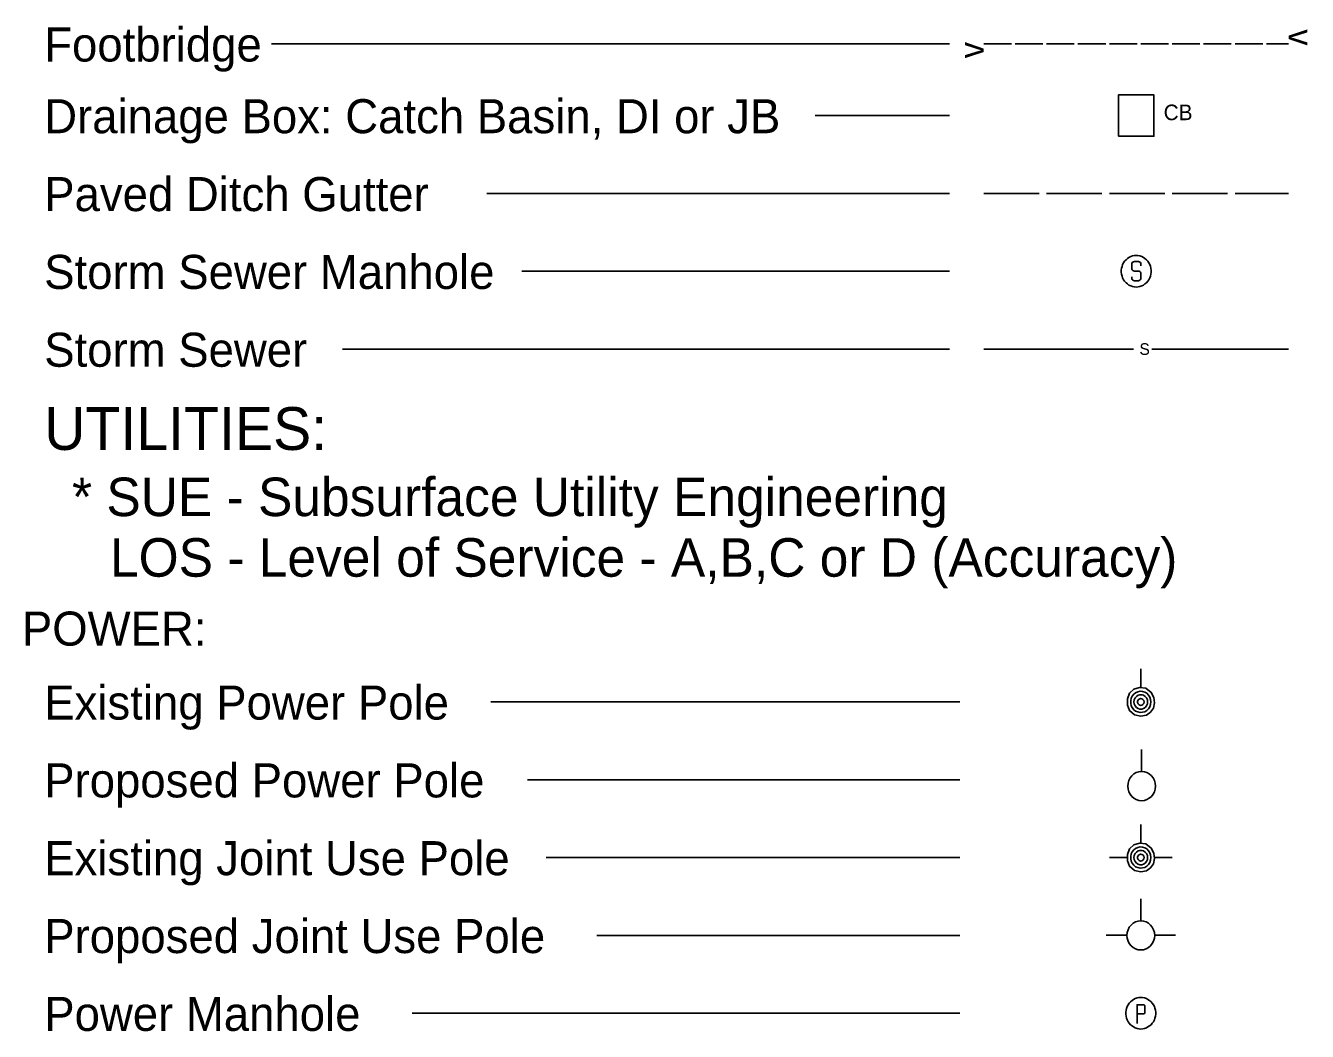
# Model space of a CAD drawing. Extents: x 2025847 to 2026166, y 840763 to 840870.
# Drawn here: x 2026099 to 2026127.55, y 840824.21 to 840846.6 of the extents above; entities that cross this region are included whole.
import ezdxf

# ---------------------------------------------------------------- set-up
doc = ezdxf.new("R2010")
doc.units = 0
doc.layers.add('Sheet_Symbology', color=7, linetype='Continuous')

msp = doc.modelspace()

# ---------------------------------------------------------------- linework, layer by layer
at = {"layer": 'Sheet_Symbology'}
for p, q in [((2026119.578, 840846.199), (2026104.475, 840846.199)), ((2026120.343, 840846.199), (2026120.961, 840846.199)), ((2026121.043, 840846.199), (2026121.66, 840846.199)), ((2026121.743, 840846.199), (2026122.36, 840846.199)), ((2026122.442, 840846.199), (2026123.06, 840846.199)), ((2026123.142, 840846.199), (2026123.759, 840846.199)), ((2026123.842, 840846.199), (2026124.459, 840846.199)), ((2026124.541, 840846.199), (2026125.159, 840846.199)), ((2026125.241, 840846.199), (2026125.858, 840846.199)), ((2026125.941, 840846.199), (2026126.558, 840846.199)), ((2026126.64, 840846.199), (2026127.134, 840846.199)), ((2026119.578, 840844.602), (2026116.59, 840844.602)), ((2026119.578, 840842.869), (2026109.273, 840842.869)), ((2026120.343, 840842.869), (2026121.578, 840842.869)), ((2026121.743, 840842.869), (2026122.977, 840842.869)), ((2026123.142, 840842.869), (2026124.377, 840842.869)), ((2026124.541, 840842.869), (2026125.776, 840842.869)), ((2026125.941, 840842.869), (2026127.134, 840842.869)), ((2026123.64, 840841.198), (2026123.64, 840841.291)), ((2026123.699, 840841.353), (2026123.787, 840841.353)), ((2026123.843, 840841.291), (2026123.843, 840841.26)), ((2026119.578, 840841.136), (2026110.056, 840841.136)), ((2026123.64, 840841.015), (2026123.64, 840840.984)), ((2026123.787, 840841.139), (2026123.699, 840841.139)), ((2026123.699, 840840.925), (2026123.787, 840840.925)), ((2026123.843, 840840.984), (2026123.843, 840841.08)), ((2026119.578, 840839.403), (2026106.061, 840839.403)), ((2026120.343, 840839.403), (2026123.679, 840839.403)), ((2026124.091, 840839.403), (2026127.134, 840839.403)), ((2026123.842, 840831.865), (2026123.842, 840832.281)), ((2026119.807, 840831.546), (2026109.364, 840831.546)), ((2026123.859, 840829.996), (2026123.859, 840830.483)), ((2026119.807, 840829.813), (2026110.178, 840829.813)), ((2026123.842, 840828.399), (2026123.842, 840828.815)), ((2026119.807, 840828.08), (2026110.595, 840828.08)), ((2026123.538, 840828.08), (2026123.143, 840828.08)), ((2026124.146, 840828.08), (2026124.541, 840828.08)), ((2026123.842, 840826.673), (2026123.842, 840827.16)), ((2026119.807, 840826.347), (2026111.722, 840826.347)), ((2026123.533, 840826.348), (2026123.07, 840826.348)), ((2026124.15, 840826.348), (2026124.613, 840826.348)), ((2026123.935, 840824.774), (2026123.935, 840824.625)), ((2026119.807, 840824.614), (2026107.611, 840824.614)), ((2026123.909, 840824.597), (2026123.759, 840824.597))]:
    msp.add_line(p, q, dxfattribs=at)
for points in [[(2026123.343, 840844.142), (2026124.134, 840844.142), (2026124.134, 840845.063), (2026123.343, 840845.063)], [(2026123.842, 840831.226), (2026123.969, 840831.251), (2026124.054, 840831.315), (2026124.121, 840831.405), (2026124.146, 840831.526), (2026124.133, 840831.642), (2026124.073, 840831.757), (2026123.951, 840831.853), (2026123.811, 840831.865), (2026123.69, 840831.827), (2026123.593, 840831.737), (2026123.544, 840831.616), (2026123.544, 840831.475), (2026123.593, 840831.354), (2026123.702, 840831.258)], [(2026123.842, 840827.76), (2026123.969, 840827.785), (2026124.054, 840827.849), (2026124.121, 840827.939), (2026124.146, 840828.06), (2026124.133, 840828.176), (2026124.073, 840828.291), (2026123.951, 840828.387), (2026123.811, 840828.399), (2026123.69, 840828.361), (2026123.593, 840828.271), (2026123.544, 840828.15), (2026123.544, 840828.009), (2026123.593, 840827.888), (2026123.702, 840827.792)]]:
    msp.add_lwpolyline(points, close=True, dxfattribs=at)
for points in [[(2026123.739, 840841.488), (2026123.696, 840841.485), (2026123.656, 840841.477), (2026123.616, 840841.462), (2026123.578, 840841.443), (2026123.544, 840841.42), (2026123.512, 840841.392), (2026123.482, 840841.358), (2026123.458, 840841.325), (2026123.437, 840841.285), (2026123.423, 840841.243), (2026123.413, 840841.201), (2026123.407, 840841.158), (2026123.407, 840841.113), (2026123.413, 840841.071), (2026123.423, 840841.026), (2026123.437, 840840.987), (2026123.458, 840840.947), (2026123.482, 840840.914), (2026123.512, 840840.88), (2026123.544, 840840.852), (2026123.578, 840840.829), (2026123.616, 840840.81), (2026123.656, 840840.795), (2026123.699, 840840.787), (2026123.739, 840840.784), (2026123.782, 840840.787), (2026123.822, 840840.795), (2026123.862, 840840.81), (2026123.899, 840840.829), (2026123.934, 840840.852), (2026123.966, 840840.88), (2026123.996, 840840.914), (2026124.02, 840840.947), (2026124.041, 840840.987), (2026124.054, 840841.029), (2026124.065, 840841.071), (2026124.07, 840841.113), (2026124.07, 840841.158), (2026124.065, 840841.201), (2026124.054, 840841.246), (2026124.041, 840841.285), (2026124.02, 840841.325), (2026123.996, 840841.358), (2026123.966, 840841.392), (2026123.934, 840841.42), (2026123.899, 840841.443), (2026123.862, 840841.462), (2026123.822, 840841.477), (2026123.779, 840841.485), (2026123.739, 840841.488)], [(2026123.64, 840841.291), (2026123.645, 840841.311), (2026123.653, 840841.327), (2026123.664, 840841.339), (2026123.68, 840841.347), (2026123.699, 840841.353)], [(2026123.787, 840841.353), (2026123.803, 840841.347), (2026123.819, 840841.339), (2026123.832, 840841.327), (2026123.84, 840841.311), (2026123.843, 840841.291)], [(2026123.699, 840841.139), (2026123.68, 840841.142), (2026123.664, 840841.15), (2026123.653, 840841.164), (2026123.645, 840841.181), (2026123.64, 840841.198)], [(2026123.64, 840840.987), (2026123.645, 840840.967), (2026123.653, 840840.95), (2026123.664, 840840.936), (2026123.68, 840840.928), (2026123.699, 840840.925)], [(2026123.843, 840841.077), (2026123.84, 840841.097), (2026123.832, 840841.113), (2026123.819, 840841.128), (2026123.803, 840841.136), (2026123.787, 840841.139)], [(2026123.787, 840840.925), (2026123.803, 840840.928), (2026123.819, 840840.936), (2026123.832, 840840.95), (2026123.84, 840840.967), (2026123.843, 840840.987)], [(2026124.067, 840831.546), (2026124.06, 840831.603), (2026124.042, 840831.654), (2026124.012, 840831.699), (2026123.975, 840831.737), (2026123.933, 840831.763), (2026123.878, 840831.776), (2026123.829, 840831.782), (2026123.775, 840831.769), (2026123.726, 840831.75), (2026123.69, 840831.718), (2026123.653, 840831.673), (2026123.629, 840831.629), (2026123.617, 840831.571), (2026123.617, 840831.52), (2026123.629, 840831.462), (2026123.653, 840831.418), (2026123.69, 840831.373), (2026123.726, 840831.341), (2026123.775, 840831.322), (2026123.829, 840831.309), (2026123.878, 840831.315), (2026123.933, 840831.328), (2026123.975, 840831.354), (2026124.012, 840831.392), (2026124.042, 840831.437), (2026124.06, 840831.488), (2026124.067, 840831.546)], [(2026123.994, 840831.546), (2026123.988, 840831.59), (2026123.969, 840831.635), (2026123.939, 840831.667), (2026123.903, 840831.693), (2026123.866, 840831.705), (2026123.817, 840831.705), (2026123.781, 840831.693), (2026123.744, 840831.667), (2026123.714, 840831.635), (2026123.696, 840831.59), (2026123.69, 840831.546), (2026123.696, 840831.501), (2026123.714, 840831.456), (2026123.744, 840831.424), (2026123.781, 840831.398), (2026123.817, 840831.386), (2026123.866, 840831.386), (2026123.903, 840831.398), (2026123.939, 840831.424), (2026123.969, 840831.456), (2026123.988, 840831.501), (2026123.994, 840831.546)], [(2026123.915, 840831.546), (2026123.909, 840831.577), (2026123.89, 840831.603), (2026123.866, 840831.616), (2026123.836, 840831.622), (2026123.805, 840831.61), (2026123.781, 840831.59), (2026123.769, 840831.558), (2026123.769, 840831.533), (2026123.781, 840831.501), (2026123.805, 840831.481), (2026123.836, 840831.469), (2026123.866, 840831.475), (2026123.89, 840831.488), (2026123.909, 840831.514), (2026123.915, 840831.546)], [(2026124.067, 840828.08), (2026124.06, 840828.137), (2026124.042, 840828.188), (2026124.012, 840828.233), (2026123.975, 840828.271), (2026123.933, 840828.297), (2026123.878, 840828.31), (2026123.829, 840828.316), (2026123.775, 840828.303), (2026123.726, 840828.284), (2026123.69, 840828.252), (2026123.653, 840828.207), (2026123.629, 840828.163), (2026123.617, 840828.105), (2026123.617, 840828.054), (2026123.629, 840827.996), (2026123.653, 840827.952), (2026123.69, 840827.907), (2026123.726, 840827.875), (2026123.775, 840827.856), (2026123.829, 840827.843), (2026123.878, 840827.849), (2026123.933, 840827.862), (2026123.975, 840827.888), (2026124.012, 840827.926), (2026124.042, 840827.971), (2026124.06, 840828.022), (2026124.067, 840828.08)], [(2026123.994, 840828.08), (2026123.988, 840828.124), (2026123.969, 840828.169), (2026123.939, 840828.201), (2026123.903, 840828.227), (2026123.866, 840828.239), (2026123.817, 840828.239), (2026123.781, 840828.227), (2026123.744, 840828.201), (2026123.714, 840828.169), (2026123.696, 840828.124), (2026123.69, 840828.08), (2026123.696, 840828.035), (2026123.714, 840827.99), (2026123.744, 840827.958), (2026123.781, 840827.932), (2026123.817, 840827.92), (2026123.866, 840827.92), (2026123.903, 840827.932), (2026123.939, 840827.958), (2026123.969, 840827.99), (2026123.988, 840828.035), (2026123.994, 840828.08)], [(2026123.915, 840828.08), (2026123.909, 840828.111), (2026123.89, 840828.137), (2026123.866, 840828.15), (2026123.836, 840828.156), (2026123.805, 840828.144), (2026123.781, 840828.124), (2026123.769, 840828.092), (2026123.769, 840828.067), (2026123.781, 840828.035), (2026123.805, 840828.016), (2026123.836, 840828.003), (2026123.866, 840828.009), (2026123.89, 840828.022), (2026123.909, 840828.048), (2026123.915, 840828.08)], [(2026123.842, 840824.965), (2026123.799, 840824.963), (2026123.759, 840824.954), (2026123.719, 840824.94), (2026123.681, 840824.92), (2026123.647, 840824.898), (2026123.614, 840824.87), (2026123.585, 840824.836), (2026123.561, 840824.802), (2026123.54, 840824.763), (2026123.526, 840824.721), (2026123.516, 840824.678), (2026123.51, 840824.636), (2026123.51, 840824.591), (2026123.516, 840824.549), (2026123.526, 840824.504), (2026123.54, 840824.464), (2026123.561, 840824.425), (2026123.585, 840824.391), (2026123.614, 840824.357), (2026123.647, 840824.329), (2026123.681, 840824.307), (2026123.719, 840824.287), (2026123.759, 840824.273), (2026123.802, 840824.265), (2026123.842, 840824.262), (2026123.884, 840824.265), (2026123.925, 840824.273), (2026123.965, 840824.287), (2026124.002, 840824.307), (2026124.037, 840824.329), (2026124.069, 840824.357), (2026124.098, 840824.391), (2026124.122, 840824.425), (2026124.144, 840824.464), (2026124.157, 840824.507), (2026124.168, 840824.549), (2026124.173, 840824.591), (2026124.173, 840824.636), (2026124.168, 840824.678), (2026124.157, 840824.723), (2026124.144, 840824.763), (2026124.122, 840824.802), (2026124.098, 840824.836), (2026124.069, 840824.87), (2026124.037, 840824.898), (2026124.002, 840824.92), (2026123.965, 840824.94), (2026123.925, 840824.954), (2026123.882, 840824.963), (2026123.842, 840824.965)], [(2026123.759, 840824.388), (2026123.759, 840824.597), (2026123.759, 840824.802), (2026123.909, 840824.802)], [(2026123.909, 840824.802), (2026123.919, 840824.799), (2026123.927, 840824.794), (2026123.933, 840824.785), (2026123.935, 840824.774)], [(2026123.935, 840824.625), (2026123.933, 840824.614), (2026123.927, 840824.605), (2026123.919, 840824.6), (2026123.909, 840824.597)]]:
    msp.add_lwpolyline(points, dxfattribs=at)
for centre in [(2026123.859, 840829.671), (2026123.842, 840826.347)]:
    msp.add_ellipse(centre, major_axis=(0, 0.325), ratio=0.95, dxfattribs=at)

# ---------------------------------------------------------------- texts
for s, height, p in [('Footbridge', 0.7582, (2026099.414, 840845.806)), ('Drainage Box: Catch Basin, DI or JB', 0.75818, (2026099.414, 840844.209)), ('CB', 0.3466, (2026124.351, 840844.5)), ('Paved Ditch Gutter', 0.75818, (2026099.414, 840842.475)), ('Storm Sewer Manhole', 0.75818, (2026099.414, 840840.742)), ('Storm Sewer', 0.75818, (2026099.414, 840839.009)), ('S', 0.26, (2026123.811, 840839.273)), ('UTILITIES:', 0.9531, (2026099.413, 840837.157)), ('* SUE - Subsurface Utility Engineering', 0.85783, (2026100.034, 840835.683)), ('LOS - Level of Service - A,B,C or D (Accuracy) ', 0.85783, (2026100.879, 840834.334)), ('POWER:', 0.7582, (2026098.917, 840832.799)), ('Existing Power Pole', 0.75818, (2026099.414, 840831.152)), ('Proposed Power Pole', 0.75818, (2026099.414, 840829.419)), ('Existing Joint Use Pole', 0.75818, (2026099.414, 840827.687)), ('Proposed Joint Use Pole', 0.75818, (2026099.415, 840825.953)), ('Power Manhole', 0.75818, (2026099.415, 840824.22))]:
    msp.add_text(s, height=height, dxfattribs=at).set_placement(p)
for rotation, p in [(270.2288, (2026127.133, 840846.523)), (89.7712, (2026120.342, 840845.876))]:
    msp.add_text('v', height=0.543, rotation=rotation, dxfattribs=at).set_placement(p)

doc.saveas('drawing.dxf')
